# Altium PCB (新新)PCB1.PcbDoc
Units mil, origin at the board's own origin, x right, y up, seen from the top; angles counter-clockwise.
Board outline 2550 x 3860 mil, 2 copper layers (Top Layer, Bottom Layer); 26 components, 46 nets, 368 pads, 7 vias.
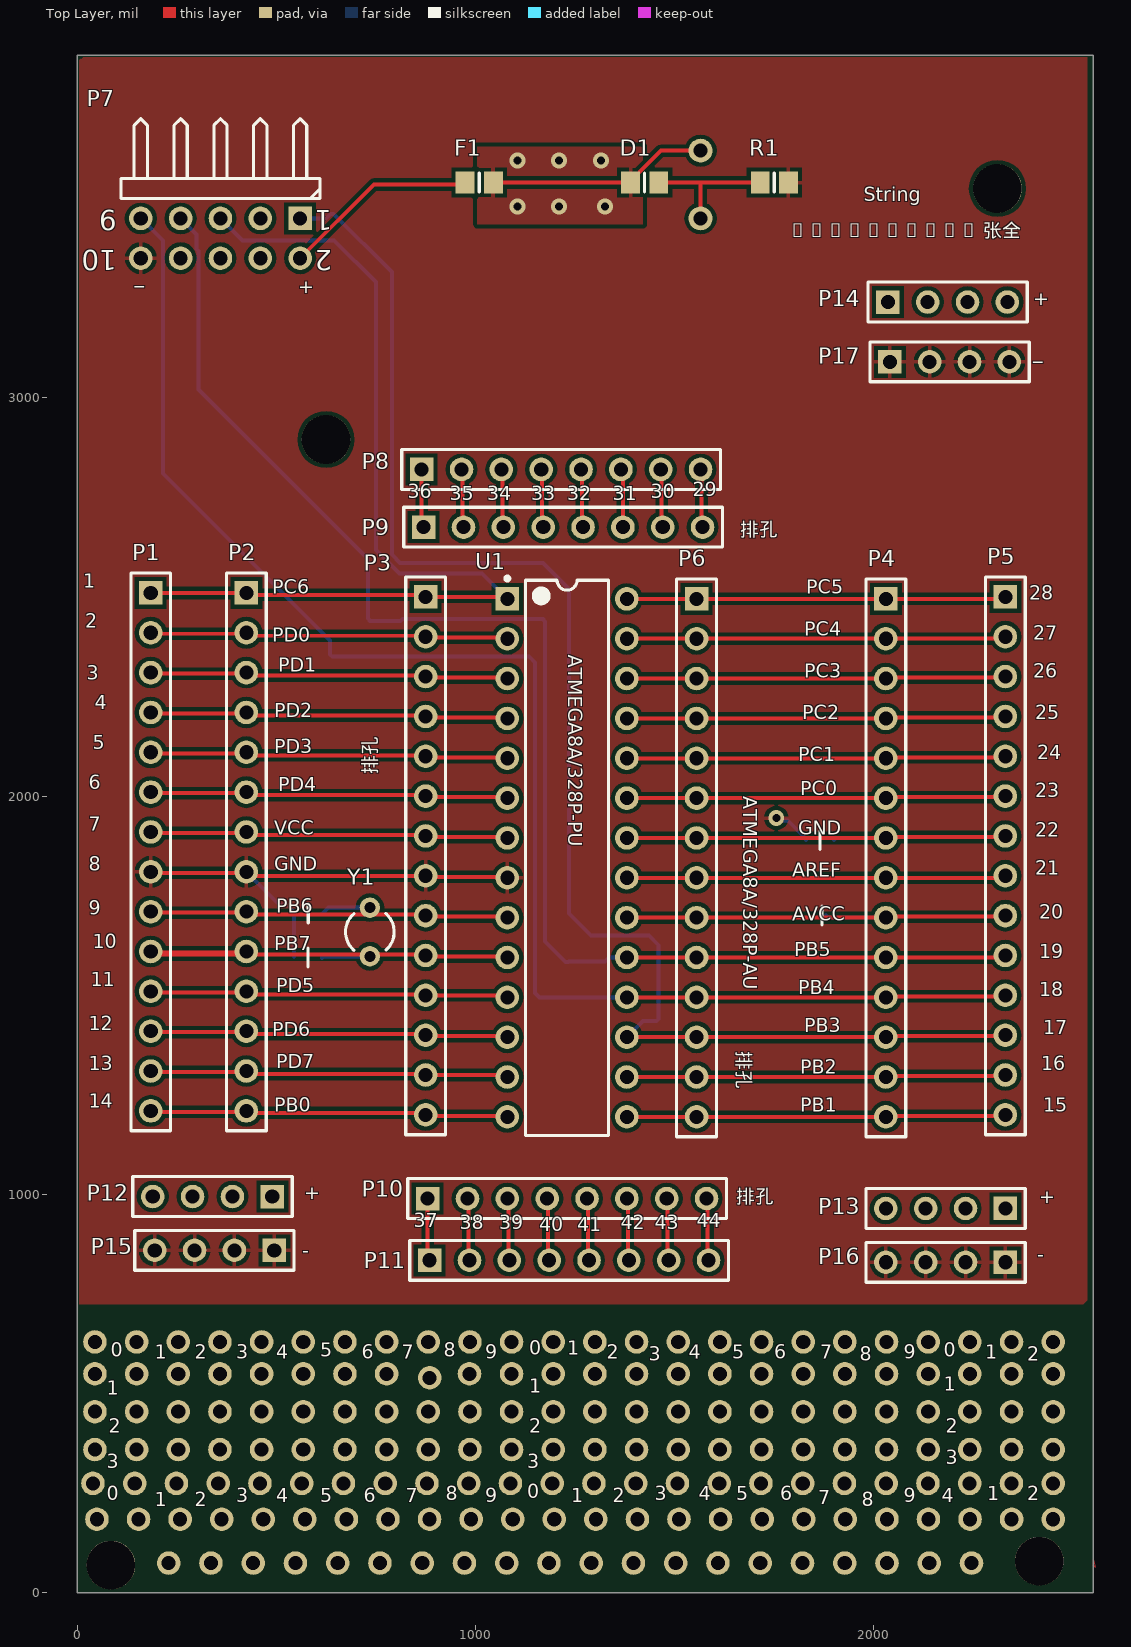
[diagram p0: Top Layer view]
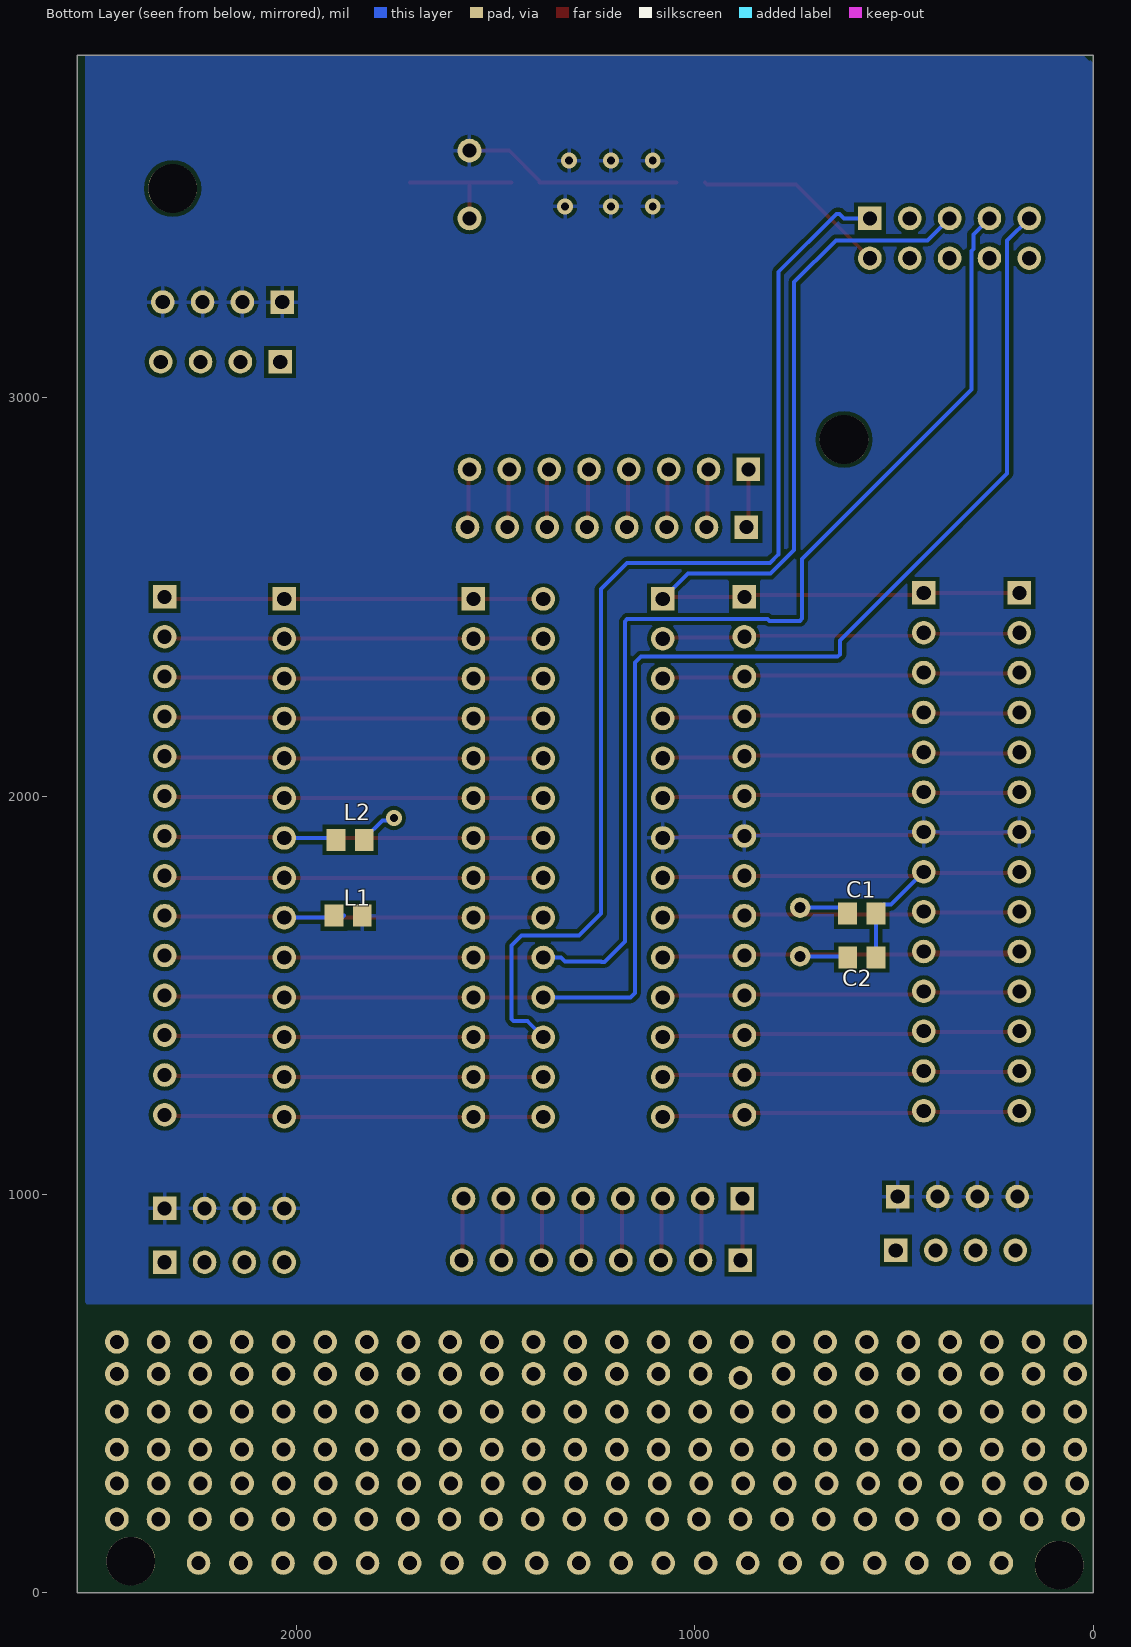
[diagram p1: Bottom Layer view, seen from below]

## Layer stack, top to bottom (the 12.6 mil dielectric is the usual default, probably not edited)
Top Solder: solder mask 0.4, Solder Resist, Dk 3.5
Top Layer: signal copper 1.4
Dielectric 1: dielectric 12.6, FR-4, Dk 4.8
Bottom Layer: signal copper 1.4
Bottom Solder: solder mask 0.4, Solder Resist, Dk 3.5

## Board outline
0,0 2550,0 2550,3860 0,3860

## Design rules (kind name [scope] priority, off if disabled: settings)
Clearance [All] p1: gap=10 ignorepadtopadclearanceinfootprint=FALSE except(0: Arc-Hole Track-Hole SMDPad-Hole THPad-Hole Via-Hole Fill-Hole Poly-Hole Region-Hole Text-Hole)
HoleSize [All] p1: absolutevalues=TRUE maxlimit=200 minlimit=1 maxpercent=80.000 minpercent=20.000
HoleToHoleClearance [All] p1: gap=0 allowstackedmicrovias=TRUE
MinimumSolderMaskSliver [All] p1: minsoldermaskwidth=4
PolygonConnect [All] p1: connectstyle=Relief reliefconductorwidth=10 reliefentries=4 polygonreliefangle="90 Angle" airgapwidth=10
RoutingVias [All] p1: holewidth=20 width=32 viastyle="Through Hole" minholewidth=16 minwidth=26 maxholewidth=28 maxwidth=50
SilkToSilkClearance [All] p1: silktosilkclearance=0
SilkToSolderMaskClearance [IsPad] p1: minsilkscreentomaskgap=0 clearancetoexposedcopper=TRUE
SolderMaskExpansion [All] p1: expansion=4
Width [All] p1: maxlimit=100 minlimit=10 preferedwidth=10 minimp=50.000000 maximp=50.000000 favimp=50.000000
25 further rules are at their usual default settings.

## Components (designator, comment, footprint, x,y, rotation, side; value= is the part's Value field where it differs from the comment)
C1 "Cap Semi" 6-0805_N#1 580.43,1705 r0 top value=22pF
C2 "Cap Semi" 6-0805_N#1 580,1595 r0 top value=22pF
D1 "LED2" 6-0805_N#2 1424.57,3540 r0 top
F1 "Fuse 1" 6-0805_N#2 1009.57,3540 r0 top
L1 "磁珠" 6-0805_N#1 1869.57,1700 r0 top
L2 "磁珠" 6-0805_N#1 1864.57,1890 r0 top
P1 "Header 14" HDR1X14 185,2510 r270 top
P2 "Header 14" HDR1X14 425,2510 r270 top
P3 "Header 14" HDR1X14 875,2500 r270 top
P4 "Header 14" HDR1X14 2030,2495 r270 top
P5 "Header 14" HDR1X14 2330,2500 r270 top
P6 "Header 14" HDR1X14 1555,2495 r270 top
P7 "Header 5X2H" HDR2X5H 560,3450 r180 top
P8 "Header 8" HDR1X8 865,2820 r0 top
P9 "Header 8" HDR1X8 870,2675 r0 top
P10 "Header 8" HDR1X8 880,990 r0 top
P11 "Header 8" HDR1X8 885,835 r0 top
P12 "Header 4" HDR1X4 490,995 r180 top
P13 "Header 4" HDR1X4 2330,965 r180 top
P14 "Header 4" HDR1X4 2035,3240 r0 top
P15 "Header 4" HDR1X4 495,860 r180 top
P16 "Header 4" HDR1X4 2330,830 r180 top
P17 "Header 4" HDR1X4 2040,3090 r0 top
R1 "Res3" 6-0805_N#2 1750,3540 r0 top value=1K
U1 "ATmega8A-PU" 28P3 1230,1845 r0 top
Y1 "11.0529~16MHz" R38 735,1658.98 r180 top

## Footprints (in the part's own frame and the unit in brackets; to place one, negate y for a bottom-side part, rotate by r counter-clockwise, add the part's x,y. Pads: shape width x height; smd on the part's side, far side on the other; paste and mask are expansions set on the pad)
6-0805_N#1 [mm] "Chip Resistor, Body 2.0x1.2mm, IPC Medium Density"
  rect 1.2x1.4 smd far side: 1(-0.9,0) 2(0.9,0)
  silkscreen extent 0,-0.6 0,0.6, body extent -1.07,-0.7 1.07,0.7, height 0.7
6-0805_N#2 [mm] "Chip Resistor, Body 2.0x1.2mm, IPC Medium Density"
  rect 1.2x1.4 smd: 1(-0.9,0) 2(0.9,0)
  silkscreen extent 0,-0.6 0,0.6, body extent -1.07,-0.7 1.07,0.7, height 0.7
28P3 [mm] "28-Pin Plastic Dual In-Line Package (PDIP)"
  rect 1.5x1.5 hole 0.9: 1(-3.81,16.51)
  round 1.5 hole 0.9: 2(-3.81,13.97) 3(-3.81,11.43) 4(-3.81,8.89) 5(-3.81,6.35) 6(-3.81,3.81) 7(-3.81,1.27) 8(-3.81,-1.27) 9(-3.81,-3.81) 10(-3.81,-6.35) 11(-3.81,-8.89) 12(-3.81,-11.43) 13(-3.81,-13.97) 14(-3.81,-16.51) 15(3.81,-16.51) 16(3.81,-13.97) 17(3.81,-11.43) 18(3.81,-8.89) 19(3.81,-6.35) 20(3.81,-3.81) 21(3.81,-1.27) 22(3.81,1.27) 23(3.81,3.81) 24(3.81,6.35) 25(3.81,8.89) 26(3.81,11.43) 27(3.81,13.97) 28(3.81,16.51)
  silkscreen extent -3.93,-17.7 2.65,17.93, body extent -3.6,-17.65 3.6,17.65, height 4.58
HDR1X4 [mm] "Connector; Header; 4 Position"
  rect 1.5x1.5 hole 0.9: 1(0,0)
  round 1.5 hole 0.9: 2(2.54,0) 3(5.08,0) 4(7.62,0)
  silkscreen extent -1.27,-1.27 8.89,1.27
HDR1X8 [mm] "Connector; Header; 8 Position"
  rect 1.5x1.5 hole 0.9: 1(0,0)
  round 1.5 hole 0.9: 2(2.54,0) 3(5.08,0) 4(7.62,0) 5(10.16,0) 6(12.7,0) 7(15.24,0) 8(17.78,0)
  silkscreen extent -1.27,-1.27 19.05,1.27
HDR1X14 [mm] "Connector; Header; 14 Position"
  rect 1.5x1.5 hole 0.9: 1(0,0)
  round 1.5 hole 0.9: 2(2.54,0) 3(5.08,0) 4(7.62,0) 5(10.16,0) 6(12.7,0) 7(15.24,0) 8(17.78,0) 9(20.32,0) 10(22.86,0) 11(25.4,0) 12(27.94,0) 13(30.48,0) 14(33.02,0)
  silkscreen extent -1.27,-1.27 34.29,1.27
HDR2X5H [mm] "Connector; Header; 5x2 Position; Right Angle"
  rect 1.5x1.5 hole 0.9: 1(0,0)
  round 1.5 hole 0.9: 2(0,2.54) 3(2.54,0) 4(2.54,2.54) 5(5.08,0) 6(5.08,2.54) 7(7.62,0) 8(7.62,2.54) 9(10.16,0) 10(10.16,2.54)
  silkscreen extent -1.27,-6.35 11.43,-1.27
R38 [mm] "Crystal, Thru-Hole; 2 Leads; Body 3.1 x 8.2 mm (Dia.xH)"
  round 1.3 hole 0.7: 1(0,1.55) 2(0,-1.55)
  silkscreen extent -1.55,-1.19 1.55,1.17

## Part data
C1 C2: "Capacitor (Semiconductor SIM Model)"
D1: "Typical RED, GREEN, YELLOW, AMBER GaAs LED"
F1: "5V 500mA"
L1 L2: library part Inductor, "Inductor"
P1 P2 P3 P4 P5 P6: "Header, 14-Pin"
P7: "Header, 5-Pin, Dual row, Right Angle"
P8 P9 P10 P11: "Header, 8-Pin"
P12 P13 P14 P15 P16 P17: "Header, 4-Pin"
R1: "Resistor"
U1: "8-bit AVR Microcontroller, 2.7-5.5V, 16MHz, 8KB Flash, 512 Bytes EEPROM, 1KB SRAM, 28-pin PDIP, Industrial Grade (-40°C to 85°C)"
Y1: library part XTAL, "Crystal Oscillator"

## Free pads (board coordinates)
  round 60 hole 35: 5(1565,3620) 6(1565,3450)
  round 59.06 hole 35.43: 9(40,275) 9(45,360) 9(45,455) 9(45,550) 9(45,630) 9(50,185) 9(230,75) 9(249.57,275) 9(254.13,360) 9(254.13,455) 9(254.13,550) 9(254.13,630) 9(258.7,185) 9(336.05,75) 9(354.35,275) 9(358.7,360) 9(358.7,455) 9(358.7,550) 9(358.7,630) 9(363.04,185) 9(654.21,75) 9(668.7,275) 9(672.39,360) 9(672.39,455) 9(672.39,550) 9(672.39,630) 9(676.09,185) 9(760.26,75) 9(773.48,275) 9(776.96,360) 9(776.96,455) 9(776.96,550) 9(776.96,630) 9(780.43,185) 9(866.32,75) 9(878.26,275) 9(881.52,360) 9(881.52,455) 9(881.52,630) 9(881.52,630) 9(884.78,185) 9(885,540) 9(885,540) 9(1078.42,75) 9(1087.83,275) 9(1090.65,360) 9(1090.65,455) 9(1090.65,550) 9(1090.65,630) 9(1093.48,185) 9(1290.53,75) 9(1297.39,275) 9(1299.78,360) 9(1299.78,455) 9(1299.78,550) 9(1299.78,630) 9(1302.17,185) 9(1502.63,75) 9(1506.96,275) 9(1508.91,360) 9(1508.91,455) 9(1508.91,550) 9(1508.91,630) 9(1510.87,185) 9(1714.74,75) 9(1716.52,275) 9(1718.04,360) 9(1718.04,455) 9(1718.04,550) 9(1718.04,630) 9(1719.56,185) 9(2030.87,275) 9(2031.74,360) 9(2031.74,455) 9(2031.74,550) 9(2031.74,630) 9(2032.61,185) 9(2032.89,75) 9(2135.65,275) 9(2136.3,360) 9(2136.3,455) 9(2136.3,550) 9(2136.3,630) 9(2136.96,185) 9(2138.95,75) 9(2345.22,275) 9(2345.43,360) 9(2345.43,455) 9(2345.43,550) 9(2345.43,630) 9(2345.65,185) ""(144.78,275) ""(149.57,360) ""(149.57,455) ""(149.57,550) ""(149.57,630) ""(154.35,185) ""(442.11,75) ""(459.13,275) ""(463.26,360) ""(463.26,455) ""(463.26,550) ""(463.26,630) ""(467.39,185) ""(548.16,75) ""(563.91,275) ""(567.83,360) ""(567.83,455) ""(567.83,550) ""(567.83,630) ""(571.74,185) ""(972.37,75) ""(983.04,275) ""(985,550) ""(985,550) ""(986.09,360) ""(986.09,455) ""(986.09,630) ""(986.09,630) ""(989.13,185) ""(1184.47,75) ""(1192.61,275) ""(1195.22,360) ""(1195.22,455) ""(1195.22,550) ""(1195.22,630) ""(1197.83,185) ""(1396.58,75) ""(1402.17,275) ""(1404.35,360) ""(1404.35,455) ""(1404.35,550) ""(1404.35,630) ""(1406.52,185) ""(1608.68,75) ""(1611.74,275) ""(1613.48,360) ""(1613.48,455) ""(1613.48,550) ""(1613.48,630) ""(1615.22,185) ""(1820.79,75) ""(1821.3,275) ""(1822.61,360) ""(1822.61,455) ""(1822.61,550) ""(1822.61,630) ""(1823.91,185) ""(1926.09,275) ""(1926.84,75) ""(1927.17,360) ""(1927.17,455) ""(1927.17,550) ""(1927.17,630) ""(1928.26,185) ""(2240.43,275) ""(2240.87,360) ""(2240.87,455) ""(2240.87,550) ""(2240.87,630) ""(2241.3,185) ""(2245,75) ""(2450,185) ""(2450,360) ""(2450,455) ""(2450,550) ""(2450,630) ""(2450,275)
  round 122 hole 122 unplated: ""(85,70) ""(625,2895) ""(2310,3525) ""(2415,80)

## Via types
v1: diameter 40, hole 20, Top Layer to Bottom Layer, 7 vias

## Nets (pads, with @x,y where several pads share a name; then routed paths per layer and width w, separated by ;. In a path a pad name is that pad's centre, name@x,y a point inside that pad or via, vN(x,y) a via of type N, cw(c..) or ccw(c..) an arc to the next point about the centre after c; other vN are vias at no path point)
NetD1_2: D1.2 pad.6 R1.1 | length 344.6
  Top Layer w10: D1.2 1565,3540 ; pad.6 1565,3540 ; R1.1 1565,3540
NetF1_1: F1.1 P7.2 | length 492.8
  Top Layer w10: P7.2 745,3535 969.13,3535 F1.1
NetP8_1: P8.1 P9.1 | length 147.1
  Top Layer w10: P8.1 865,2680 P9.1
NetP8_2: P8.2 P9.2 | length 147.1
  Top Layer w10: P8.2 967.5,2817.5 967.5,2677.5 P9.2
NetP8_3: P8.3 P9.3 | length 147.1
  Top Layer w10: P8.3 1067.5,2817.5 1067.5,2677.5 P9.3
NetP8_4: P8.4 P9.4 | length 147.1
  Top Layer w10: P8.4 1167.5,2817.5 1167.5,2677.5 P9.4
NetP8_5: P8.5 P9.5 | length 147.1
  Top Layer w10: P8.5 1267.5,2817.5 1267.5,2677.5 P9.5
NetP8_6: P8.6 P9.6 | length 147.1
  Top Layer w10: P8.6 1370,2815 P9.6
NetP8_7: P8.7 P9.7 | length 147.1
  Top Layer w10: P8.7 1467.5,2817.5 1467.5,2677.5 P9.7
NetP8_8: P8.8 P9.8 | length 147.1
  Top Layer w10: P8.8 1567.5,2817.5 1567.5,2677.5 P9.8
NetP10_1: P10.1 P11.1 | length 157.1
  Top Layer w10: P10.1 880,840 P11.1
NetP10_2: P10.2 P11.2 | length 157.1
  Top Layer w10: P10.2 982.5,987.5 982.5,837.5 P11.2
NetP10_3: P10.3 P11.3 | length 157.1
  Top Layer w10: P10.3 1082.5,987.5 1082.5,837.5 P11.3
NetP10_4: P10.4 P11.4 | length 157.1
  Top Layer w10: P10.4 1182.5,987.5 1182.5,837.5 P11.4
NetP10_5: P10.5 P11.5 | length 157.1
  Top Layer w10: P10.5 1282.5,987.5 1282.5,837.5 P11.5
NetP10_6: P10.6 P11.6 | length 157.1
  Top Layer w10: P10.6 1382.5,987.5 1382.5,837.5 P11.6
NetP10_7: P10.7 P11.7 | length 157.1
  Top Layer w10: P10.7 1482.5,987.5 1482.5,837.5 P11.7
NetP10_8: P10.8 P11.8 | length 157.1
  Top Layer w10: P10.8 1582.5,987.5 1582.5,837.5 P11.8
PIN1: P1.1 P2.1 P3.1 P7.5 U1.1 | length 2410.7
  Top Layer w10: P1.1 P2.1 435,2510 440,2505 870,2505 P3.1 1075,2500 U1.1
  Bottom Layer w10: P7.5 415,3395 645,3395 750,3290 750,2617.57 809.02,2558.55 1016.45,2558.55 U1.1
PIN2: P1.2 P2.2 P3.2 U1.2 | length 901.2
  Top Layer w10: P1.2 187.5,2407.5 430,2407.5 435,2402.5 872.5,2402.5 P3.2 877.5,2397.5 1077.5,2397.5 U1.2
PIN3: P1.3 P2.3 P3.3 U1.3 | length 901.2
  Top Layer w10: P1.3 187.5,2307.5 437.5,2307.5 440,2305 442.5,2302.5 872.5,2302.5 P3.3 877.5,2297.5 1077.5,2297.5 U1.3
PIN4: P1.4 P2.4 P3.4 U1.4 | length 901.2
  Top Layer w10: P1.4 187.5,2207.5 437.5,2207.5 440,2205 442.5,2202.5 872.5,2202.5 P3.4 877.5,2197.5 1077.5,2197.5 U1.4
PIN5: P1.5 P2.5 P3.5 U1.5 | length 901.2
  Top Layer w10: P1.5 187.5,2107.5 437.5,2107.5 440,2105 442.5,2102.5 872.5,2102.5 P3.5 877.5,2097.5 1077.5,2097.5 U1.5
PIN6: P1.6 P2.6 P3.6 U1.6 | length 901.2
  Top Layer w10: P1.6 187.5,2007.5 437.5,2007.5 440,2005 442.5,2002.5 872.5,2002.5 P3.6 877.5,1997.5 1077.5,1997.5 U1.6
PIN7: D1.1 F1.2 L1.1 P1.7 P2.7 P3.7 P12.1 P12.2 P12.3 P12.4 P13.1 P13.2 P13.3 P13.4 P14.1 P14.2 P14.3 P14.4 pad.5 U1.7 | length 1456.7
  Top Layer w10: P1.7 187.5,1907.5 437.5,1907.5 442.5,1902.5 872.5,1902.5 P3.7 877.5,1897.5 1077.5,1897.5 U1.7 ; F1.2 D1.1 1389.13,3543.94 1465.2,3620 pad.5
  other v1: 1105,3480 1210,3480 1325,3480 1105,3595 1210,3595 1315,3595
PIN8: C1.1 C2.1 L2.1 P1.8 P2.8 P3.8 P7.10 P15.1 P15.2 P15.3 P15.4 P16.1 P16.2 P16.3 P16.4 P17.1 P17.2 P17.3 P17.4 R1.2 U1.8 | length 1274.1
  Top Layer w10: P1.8 187.5,1807.5 437.5,1807.5 445,1800 P3.8 877.5,1797.5 1077.5,1797.5 U1.8
  Bottom Layer w10: P2.8 507.44,1727.56 526.38,1727.56 544.57,1709.37 C2.1@544.57,1596.97 ; v1(1755,1945) 1760.74,1939.26 1783.81,1939.26 1829.13,1893.94 L2.1
PIN9: C1.2 P1.9 P2.9 P3.9 U1.9 Y1.2 | length 1045.7
  Top Layer w10: P1.9 187.5,1707.5 437.5,1707.5 442.5,1702.5 735,1702.5 872.5,1702.5 P3.9 877.5,1697.5 1077.5,1697.5 U1.9
  Bottom Layer w10: C1.2 630.87,1720 Y1.2 735,1725 Y1.2@745,1735
PIN10: C2.2 P1.10 P2.10 P3.10 U1.10 Y1.1 | length 1276.8
  Top Layer w10: P1.10 187.5,1607.5 437.5,1607.5 P2.10@442.5,1602.5 ; P1.10@192.5,1602.5 735,1602.5 872.5,1602.5 P3.10 877.5,1597.5 1077.5,1597.5 U1.10
  Bottom Layer w10: C2.2@615.43,1596.97 615.43,1593.03 620.35,1597.95 Y1.1
PIN11: P1.11 P2.11 P3.11 U1.11 | length 901.2
  Top Layer w10: P1.11 187.5,1507.5 437.5,1507.5 440,1505 442.5,1502.5 872.5,1502.5 P3.11 1075,1500 U1.11
PIN12: P1.12 P2.12 P3.12 U1.12 | length 901.2
  Top Layer w10: P1.12 187.5,1407.5 437.5,1407.5 440,1405 442.5,1402.5 872.5,1402.5 P3.12 877.5,1397.5 1077.5,1397.5 U1.12
PIN13: P1.13 P2.13 P3.13 U1.13 | length 901.2
  Top Layer w10: P1.13 187.5,1307.5 437.5,1307.5 440,1305 442.5,1302.5 872.5,1302.5 P3.13 1075,1300 U1.13
PIN14: P1.14 P2.14 P3.14 U1.14 | length 901.2
  Top Layer w10: P1.14 187.5,1207.5 437.5,1207.5 440,1205 870,1205 P3.14 877.5,1197.5 1077.5,1197.5 U1.14
PIN15: P4.14 P5.14 P6.14 U1.15 | length 952.1
  Top Layer w10: U1.15 P6.14 P4.14 2032.5,1197.5 2327.5,1197.5 P5.14
PIN16: P4.13 P5.13 P6.13 U1.16 | length 952.1
  Top Layer w10: U1.16 P6.13 P4.13 2032.5,1297.5 2327.5,1297.5 P5.13
PIN17: P4.12 P5.12 P6.12 P7.1 U1.17 | length 3793
  Top Layer w10: U1.17 P6.12 P4.12 2032.5,1397.5 2327.5,1397.5 P5.12
  Bottom Layer w10: P7.1 625,3450 635.86,3460.86 644.14,3460.86 790,3315 790,2605.86 810.86,2585 1170,2585 1235,2520 1235,1705 1290,1650 1435,1650 1460,1625 1460,1440.86 1454.14,1435 1420,1435 U1.17
PIN18: P4.11 P5.11 P6.11 P7.9 U1.18 | length 3830.2
  Top Layer w10: U1.18 P6.11 P4.11 2032.5,1497.5 2327.5,1497.5 P5.11
  Bottom Layer w10: P7.9 215.47,3394.53 215.47,2809.53 635,2390 635,2355.86 640.86,2350 1135,2350 1150,2335 1150,1505.86 1160.86,1495 U1.18
PIN19: P4.10 P5.10 P6.10 P7.7 U1.19 | length 3636.9
  Top Layer w10: U1.19 P6.10 P4.10 2325,1595 P5.10
  Bottom Layer w10: P7.7 300,3410 300,3372.97 304.53,3368.44 304.53,3020.47 730,2595 730,2445.86 735.86,2440 812.39,2440 816.91,2444.53 1169.14,2444.53 1175,2438.67 1175,1635 1225.86,1584.14 1234.14,1584.14 1235,1585 1325.47,1585 1335.47,1595 U1.19
PIN20: L1.2 P4.9 P5.9 P6.9 U1.20 | length 1104.1
  Top Layer w10: U1.20 P6.9 P4.9 2032.5,1697.5 2327.5,1697.5 P5.9
  Bottom Layer w10: 1880,1700 1885,1695 P4.9
PIN21: P4.8 P5.8 P6.8 U1.21 | length 952.1
  Top Layer w10: U1.21 P6.8 P4.8 2325,1795 P5.8
PIN22: L2.2 P4.7 P5.7 P6.7 U1.22 | length 1084.1
  Top Layer w10: U1.22 P6.7 P4.7 2032.5,1897.5 2327.5,1897.5 P5.7
  Bottom Layer w10: L2.2 1905,1895 P4.7
PIN23: P4.6 P5.6 P6.6 U1.23 | length 952.1
  Top Layer w10: U1.23 P6.6 P4.6 2032.5,1997.5 2327.5,1997.5 P5.6
PIN24: P4.5 P5.5 P6.5 U1.24 | length 952.1
  Top Layer w10: U1.24 P6.5 P4.5 2032.5,2097.5 2327.5,2097.5 P5.5
PIN25: P4.4 P5.4 P6.4 U1.25 | length 952.1
  Top Layer w10: U1.25 P6.4 P4.4 2032.5,2197.5 2327.5,2197.5 P5.4
PIN26: P4.3 P5.3 P6.3 U1.26 | length 952.1
  Top Layer w10: U1.26 P6.3 P4.3 2032.5,2297.5 2327.5,2297.5 P5.3
PIN27: P4.2 P5.2 P6.2 U1.27 | length 952.1
  Top Layer w10: U1.27 P6.2 P4.2 2325,2395 P5.2
PIN28: P4.1 P5.1 P6.1 U1.28 | length 952.1
  Top Layer w10: U1.28 P6.1 P4.1 2325,2495 P5.1
pads on no net: P7.3 P7.4 P7.6 P7.8

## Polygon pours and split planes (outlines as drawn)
PIN8 on Top Layer "Top Layer-PIN8" (solid, pour order 38): 10,3850 15,3855 2535,3855 2535,735 2525,725 5,725 5,3855
no net on Top Layer "Top Layer-No Net" (solid, pour order 20): 2555,65 2550,70 2550,85
no net on Top Layer "Top Layer-No Net 1" (solid, pour order 14): 1410,3140
PIN7 on Top Layer "Top Layer-PIN7" (solid, pour order 12): 1420,3435 1420,3630 1005,3630 1005,3435
no net on Top Layer "Top Layer-No Net 2" (solid, pour order 10): 1420,3435
no net on Top Layer "Top Layer-No Net 3" (solid, pour order 6): 1110,3715
PIN7 on Bottom Layer "Bottom Layer-PIN7 3" (solid, pour order 40): 10,3845 25,3860 2530,3860 2530,730 2525,725 0,725 0,3840 20,3860
PIN7 on Bottom Layer "Bottom Layer-PIN7" (solid, pour order 46): 20,3860
PIN7 on Bottom Layer "Bottom Layer-PIN7 1" (solid, pour order 44): 20,3860
PIN7 on Bottom Layer "Bottom Layer-PIN7 2" (solid, pour order 42): 20,3860
PIN7 on Bottom Layer "Bottom Layer-PIN7 4" (solid, pour order 36): 125,3795

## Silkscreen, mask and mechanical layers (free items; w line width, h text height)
Top Overlay:
  text "String" at 1975,3480 h60
  text "PB22061324 张全" at 1785,3390 h60
  text "_" at 145,3275 h60
  text "+" at 555,3250 h60
  text "+" at 2400,3220 h60
  text "_" at 2400,3085 h60
  text "29" at 1545,2740 h60
  text "36" at 830,2735 h60
  text "30" at 1440,2735 h60
  text "35" at 935,2730 h60
  text "34" at 1030,2730 h60
  text "33" at 1140,2730 h60
  text "32" at 1230,2730 h60
  text "31" at 1345,2730 h60
  text "排孔" at 1665,2640 h60
  text "1" at 15,2510 h60
  text "PC6" at 490,2495 h60
  text "PC5" at 1830,2495 h60
  text "28" at 2390,2480 h60
  text "2" at 20,2410 h60
  text "PC4" at 1825,2390 h60
  text "27" at 2400,2380 h60
  text "PD0" at 490,2375 h60
  text "ATMEGA8A/328P-PU" at 1220,2355 h60 r270
  text "PD1" at 505,2300 h60
  text "PC3" at 1825,2285 h60
  text "26" at 2400,2285 h60
  text "3" at 25,2280 h60
  text "4" at 45,2205 h60
  text "PD2" at 495,2185 h60
  text "PC2" at 1820,2180 h60
  text "25" at 2405,2180 h60
  text "5" at 40,2105 h60
  text "PD3" at 495,2095 h60
  text "24" at 2410,2080 h60
  text "PC1" at 1810,2075 h60
  text "排孔" at 765,2055 h60 r90
  text "6" at 30,2005 h60
  text "PD4" at 505,2000 h60
  text "ATMEGA8A/328P-AU" at 1660,2000 h60 r270
  text "PC0" at 1815,1990 h60
  text "23" at 2405,1985 h60
  text "7" at 30,1900 h60
  text "VCC" at 495,1890 h60
  text "GND" at 1810,1890 h60
  text "22" at 2405,1885 h60
  text "8" at 30,1800 h60
  text "GND" at 495,1800 h60
  text "21" at 2405,1790 h60
  text "AREF" at 1795,1785 h60
  text "PB6" at 500,1695 h60
  text "9" at 30,1690 h60
  text "20" at 2415,1680 h60
  text "AVCC" at 1795,1675 h60
  text "10" at 40,1605 h60
  text "PB7" at 495,1600 h60
  text "PB5" at 1800,1585 h60
  text "19" at 2415,1580 h60
  text "11" at 35,1510 h60
  text "PD5" at 500,1495 h60
  text "PB4" at 1810,1490 h60
  text "18" at 2415,1485 h60
  text "12" at 30,1400 h60
  text "PB3" at 1825,1395 h60
  text "17" at 2425,1390 h60
  text "PD6" at 490,1385 h60
  text "排孔" at 1645,1360 h60 r270
  text "PD7" at 500,1305 h60
  text "13" at 30,1300 h60
  text "16" at 2420,1300 h60
  text "PB2" at 1815,1290 h60
  text "14" at 30,1205 h60
  text "PB0" at 495,1195 h60
  text "PB1" at 1815,1195 h60
  text "15" at 2425,1195 h60
  text "+" at 570,975 h60
  text "排孔" at 1655,965 h60
  text "+" at 2415,965 h60
  text "37" at 845,905 h60
  text "44" at 1555,905 h60
  text "38" at 960,900 h60
  text "39" at 1060,900 h60
  text "42" at 1365,900 h60
  text "43" at 1450,900 h60
  text "40" at 1160,895 h60
  text "41" at 1255,895 h60
  text "-" at 565,830 h60
  text "-" at 2410,820 h60
  text "0" at 1135,585 h60
  text "1" at 1230,585 h60
  text "0" at 85,580 h60
  text "5" at 610,580 h60
  text "8" at 920,580 h60
  text "0" at 2175,580 h60
  text "1" at 195,575 h60
  text "2" at 295,575 h60
  text "3" at 400,575 h60
  text "4" at 500,575 h60
  text "6" at 715,575 h60
  text "7" at 815,575 h60
  text "9" at 1025,575 h60
  text "2" at 1330,575 h60
  text "4" at 1535,575 h60
  text "5" at 1645,575 h60
  text "6" at 1750,575 h60
  text "7" at 1865,575 h60
  text "9" at 2075,575 h60
  text "1" at 2280,575 h60
  text "3" at 1435,570 h60
  text "8" at 1965,570 h60
  text "2" at 2385,570 h60
  text "1" at 2175,495 h60
  text "1" at 1135,490 h60
  text "1" at 75,485 h60
  text "2" at 80,390 h60
  text "2" at 1135,390 h60
  text "2" at 2180,390 h60
  text "3" at 2180,310 h60
  text "3" at 75,300 h60
  text "3" at 1130,300 h60
  text "0" at 1130,225 h60
  text "0" at 75,220 h60
  text "8" at 925,220 h60
  text "3" at 1450,220 h60
  text "4" at 1560,220 h60
  text "5" at 1655,220 h60
  text "6" at 1765,220 h60
  text "1" at 2285,220 h60
  text "2" at 2385,220 h60
  text "3" at 400,215 h60
  text "4" at 500,215 h60
  text "5" at 610,215 h60
  text "6" at 720,215 h60
  text "7" at 825,215 h60
  text "9" at 1025,215 h60
  text "1" at 1240,215 h60
  text "2" at 1345,215 h60
  text "9" at 2075,215 h60
  text "4" at 2170,215 h60
  text "7" at 1860,210 h60
  text "1" at 195,205 h60
  text "2" at 295,205 h60
  text "8" at 1970,205 h60
Mechanical 1:
  lines w10: 0,0 0,3860 2550,3860 2550,3285 2550,0 0,0

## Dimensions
0,3860 to 0,0 on Mechanical 1
0,3860 to 2550,3860 on Mechanical 1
